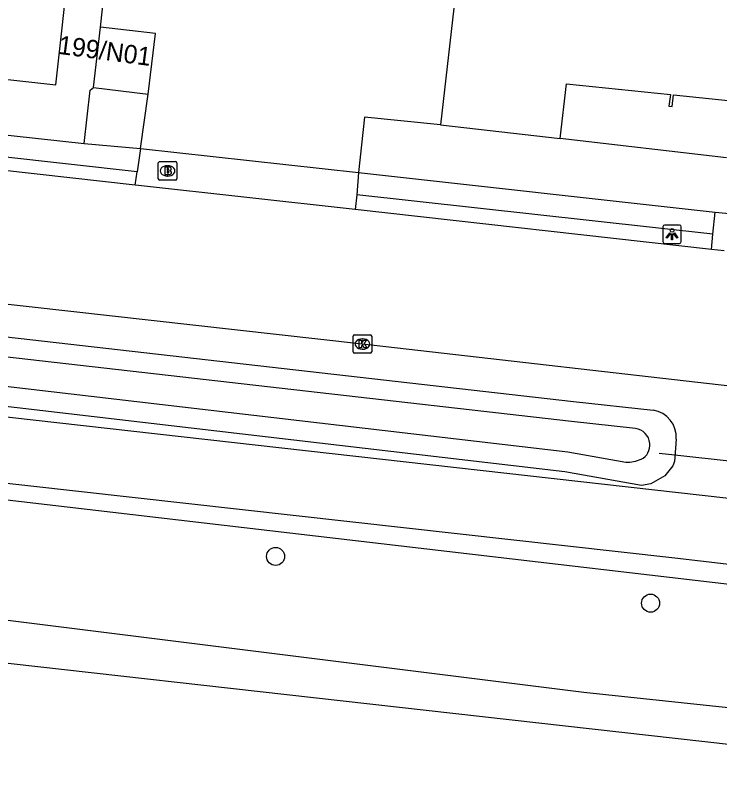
# Model space of a CAD drawing. Extents: x 161389 to 162585, y 388479 to 389761.
# Drawn here: x 162279.11 to 162317.29, y 388652.05 to 388693.41 of the extents above; entities that cross this region are included whole.
import ezdxf

# ---------------------------------------------------------------- set-up
doc = ezdxf.new("R2010")
doc.units = 0
for name, color, linetype in [('IMGEO_Berm_groen', 7, 'Continuous'), ('IMGEO_Boom', 7, 'Continuous'), ('IMGEO_Brandkraan', 7, 'Continuous'), ('IMGEO_Duiker', 7, 'Continuous'), ('IMGEO_Fietspad_gesloten', 7, 'Continuous'), ('IMGEO_Groenvoorziening', 7, 'Continuous'), ('IMGEO_Kolk', 7, 'Continuous'), ('IMGEO_Lichtpunt', 7, 'Continuous'), ('IMGEO_Pand', 7, 'Continuous'), ('IMGEO_Pand_nummerreeks', 7, 'Continuous'), ('IMGEO_Rijbaan_lokaal_gesloten', 7, 'Continuous'), ('IMGEO_Rijbaan_lokaal_open', 7, 'Continuous'), ('IMGEO_Voetpad_open', 7, 'Continuous'), ('IMGEO_Waterloop', 7, 'Continuous')]:
    doc.layers.add(name, color=color, linetype=linetype)

msp = doc.modelspace()

# ---------------------------------------------------------------- linework, layer by layer
at = {"layer": 'IMGEO_Berm_groen'}
for points in [[(162195.511, 388685.399), (162199.258, 388685.044), (162309.372, 388672.493), (162313.677, 388672.019)], [(162314.929, 388670.455), (162314.838, 388669.228), (162314.739, 388669.003), (162314.316, 388668.451), (162313.561, 388668.026), (162313.044, 388667.945), (162308.893, 388668.677), (162198.797, 388681.534), (162194.824, 388681.685), (162194.516, 388681.817), (162194.124, 388682.146), (162193.837, 388682.714), (162193.797, 388682.968), (162193.974, 388684.393)], [(162244.211, 388671.327), (162267.366, 388668.474), (162328.021, 388661.404)]]:
    msp.add_lwpolyline(points, dxfattribs=at)
msp.add_arc((162313.459, 388670.561), 1.474, 355.8563, 81.4991, dxfattribs=at)
at = {"layer": 'IMGEO_Boom'}
for centre in [(162293.214, 388664.093), (162313.541, 388661.562)]:
    msp.add_circle(centre, 0.489, dxfattribs=at)
at = {"layer": 'IMGEO_Brandkraan'}
for p, q in [((162286.934, 388685.481), (162287.786, 388685.481)), ((162286.859, 388684.555), (162286.859, 388685.407)), ((162287.347, 388685.261), (162287.372, 388685.261)), ((162287.86, 388685.407), (162287.86, 388684.555)), ((162287.37, 388684.701), (162287.345, 388684.701)), ((162287.786, 388684.481), (162286.934, 388684.481))]:
    msp.add_line(p, q, dxfattribs=at)
for points in [[(162286.934, 388685.481), (162287.786, 388685.481)], [(162286.859, 388684.555), (162286.859, 388685.407)], [(162287.207, 388685.181), (162287.207, 388684.781), (162287.42, 388684.781)], [(162287.438, 388685.181), (162287.207, 388685.181)], [(162287.386, 388685.1), (162287.332, 388685.1), (162287.332, 388685.024)], [(162287.86, 388685.407), (162287.86, 388684.555)], [(162287.332, 388685.024), (162287.385, 388685.024)], [(162287.394, 388684.948), (162287.332, 388684.948), (162287.332, 388684.867)], [(162287.332, 388684.867), (162287.394, 388684.867)], [(162287.786, 388684.481), (162286.934, 388684.481)]]:
    msp.add_lwpolyline(points, dxfattribs=at)
for centre, radius, start, end in [((162286.936, 388685.405), 0.0765, 91.552, 178.448), ((162286.936, 388685.405), 0.0765, 91.552, 178.448), ((162287.784, 388685.405), 0.0765, 1.552, 88.448), ((162287.784, 388685.405), 0.0765, 1.552, 88.448), ((162287.387, 388685.062), 0.0379, 267.8285, 90.9355), ((162287.442, 388685.036), 0.145, 59.4692, 91.5367), ((162287.467, 388685.083), 0.0922, 285.5137, 58.1501), ((162287.395, 388684.907), 0.0404, 269.8759, 90.5077), ((162287.426, 388685.032), 0.251, 268.6676, 293.5347), ((162287.472, 388684.891), 0.105, 301.3115, 78.989), ((162286.936, 388684.557), 0.0765, 181.552, 268.448), ((162286.936, 388684.557), 0.0765, 181.552, 268.448), ((162287.784, 388684.557), 0.0765, 271.552, 358.448), ((162287.784, 388684.557), 0.0765, 271.552, 358.448)]:
    msp.add_arc(centre, radius, start, end, dxfattribs=at)
for centre, major_axis, ratio, start_param, end_param in [((162287.346, 388684.981), (-0.387, 0.002), 0.722429, 4.712389, 7.853982), ((162287.371, 388684.981), (-0.39, 0.002), 0.717154, 1.570796, 4.712389)]:
    msp.add_ellipse(centre, major_axis=major_axis, ratio=ratio, start_param=start_param, end_param=end_param, dxfattribs=at)
at = {"layer": 'IMGEO_Duiker'}
msp.add_lwpolyline([(162351.516, 388665.549), (162350.544, 388665.656), (162342.711, 388666.516), (162342.022, 388666.592), (162328.189, 388668.111), (162327.769, 388668.157), (162314.864, 388669.574), (162314.015, 388669.667)], dxfattribs=at)
at = {"layer": 'IMGEO_Fietspad_gesloten'}
for points in [[(162190.209, 388681.612), (162327.081, 388666.21), (162327.212, 388666.322), (162327.332, 388666.446), (162327.44, 388666.58), (162327.536, 388666.723), (162327.619, 388666.874), (162327.689, 388667.031), (162327.743, 388667.195), (162327.783, 388667.362), (162327.808, 388667.533), (162327.818, 388667.705), (162327.812, 388667.877), (162327.791, 388668.048), (162327.769, 388668.157), (162327.723, 388668.324), (162327.662, 388668.485), (162327.587, 388668.641), (162327.498, 388668.789), (162327.396, 388668.929), (162327.347, 388668.988)], [(162328.163, 388662.672), (162327.44, 388662.75), (162327.383, 388662.532), (162314.863, 388664.007), (162212.05, 388675.493)]]:
    msp.add_lwpolyline(points, dxfattribs=at)
at = {"layer": 'IMGEO_Groenvoorziening'}
msp.add_lwpolyline([(162327.291, 388654.887), (162309.928, 388656.723), (162266.988, 388662.085), (162242.291, 388665.501), (162242.681, 388666.67)], dxfattribs=at)
at = {"layer": 'IMGEO_Kolk'}
for p, q in [((162297.424, 388675.175), (162297.424, 388676.027)), ((162297.499, 388676.101), (162298.351, 388676.101)), ((162298.425, 388676.027), (162298.425, 388675.175)), ((162297.912, 388675.881), (162297.937, 388675.881)), ((162297.935, 388675.321), (162297.91, 388675.321)), ((162298.351, 388675.101), (162297.499, 388675.101))]:
    msp.add_line(p, q, dxfattribs=at)
for points in [[(162297.424, 388675.175), (162297.424, 388676.027)], [(162297.499, 388676.101), (162298.351, 388676.101)], [(162298.425, 388676.027), (162298.425, 388675.175)], [(162297.745, 388675.801), (162297.868, 388675.801), (162297.868, 388675.65), (162297.998, 388675.801), (162298.162, 388675.801), (162298.016, 388675.65), (162298.169, 388675.401), (162298.017, 388675.401), (162297.932, 388675.565), (162297.868, 388675.498), (162297.868, 388675.401), (162297.745, 388675.401), (162297.745, 388675.801)], [(162298.351, 388675.101), (162297.499, 388675.101)]]:
    msp.add_lwpolyline(points, dxfattribs=at)
for centre, start, end in [((162297.501, 388676.025), 91.552, 178.448), ((162297.501, 388676.025), 91.552, 178.448), ((162298.349, 388676.025), 1.552, 88.448), ((162298.349, 388676.025), 1.552, 88.448), ((162297.501, 388675.177), 181.552, 268.448), ((162297.501, 388675.177), 181.552, 268.448), ((162298.349, 388675.177), 271.552, 358.448), ((162298.349, 388675.177), 271.552, 358.448)]:
    msp.add_arc(centre, 0.0765, start, end, dxfattribs=at)
for centre, major_axis, ratio, start_param, end_param in [((162297.911, 388675.601), (-0.387, 0.002), 0.722429, 4.712389, 7.853982), ((162297.936, 388675.601), (-0.39, 0.002), 0.717154, 1.570796, 4.712389)]:
    msp.add_ellipse(centre, major_axis=major_axis, ratio=ratio, start_param=start_param, end_param=end_param, dxfattribs=at)
at = {"layer": 'IMGEO_Lichtpunt'}
for p, q in [((162314.205, 388681.953), (162314.205, 388681.146)), ((162314.205, 388681.953), (162314.205, 388681.146)), ((162315.107, 388682.048), (162314.299, 388682.048)), ((162315.107, 388682.048), (162314.299, 388682.048)), ((162315.201, 388681.146), (162315.201, 388681.953)), ((162315.201, 388681.146), (162315.201, 388681.953)), ((162314.299, 388681.052), (162315.107, 388681.052)), ((162314.299, 388681.052), (162315.107, 388681.052))]:
    msp.add_line(p, q, dxfattribs=at)
for points in [[(162314.579, 388681.617), (162314.618, 388681.589), (162314.43, 388681.327), (162314.392, 388681.354), (162314.579, 388681.617)], [(162314.681, 388681.569), (162314.728, 388681.569), (162314.728, 388681.247), (162314.681, 388681.247), (162314.681, 388681.569)], [(162314.791, 388681.589), (162314.829, 388681.616), (162315.016, 388681.354), (162314.977, 388681.326), (162314.791, 388681.589)]]:
    msp.add_lwpolyline(points, dxfattribs=at)
msp.add_circle((162314.704, 388681.751), 0.0994, dxfattribs=at)
for centre, start, end in [((162314.299, 388681.953), 90, 180), ((162314.299, 388681.953), 90, 180), ((162315.107, 388681.953), 0, 90), ((162315.107, 388681.953), 0, 90), ((162314.299, 388681.146), 180, 270), ((162314.299, 388681.146), 180, 270), ((162315.107, 388681.146), 270, 0), ((162315.107, 388681.146), 270, 360)]:
    msp.add_arc(centre, 0.0946, start, end, dxfattribs=at)
at = {"layer": 'IMGEO_Pand'}
for points in [[(162266.146, 388697.835), (162265.455, 388691.401), (162281.314, 388689.643), (162282.073, 388696.501), (162284.111, 388696.275)], [(162297.05, 388695.111), (162302.955, 388694.443), (162302.151, 388687.471)], [(162283.34, 388689.498), (162283.731, 388692.772)], [(162286.316, 388689.142), (162286.707, 388692.416), (162283.731, 388692.772)], [(162308.649, 388686.731), (162308.988, 388689.701), (162314.627, 388689.125), (162314.534, 388688.49), (162314.719, 388688.469), (162314.789, 388689.095), (162320.535, 388688.495), (162320.465, 388687.859), (162320.653, 388687.85), (162320.683, 388688.479), (162325.071, 388688.022)], [(162283.34, 388689.498), (162286.316, 388689.142)], [(162302.151, 388687.471), (162308.649, 388686.731)], [(162323.903, 388652.051), (162324.031, 388653.194), (162250.099, 388661.511), (162249.582, 388661.569), (162249.555, 388661.32)]]:
    msp.add_lwpolyline(points, dxfattribs=at)
at = {"layer": 'IMGEO_Rijbaan_lokaal_gesloten'}
for points in [[(162190.731, 388687.591), (162191.691, 388687.487), (162192.948, 388687.248), (162200.409, 388686.41), (162212.852, 388685.186), (162234.573, 388682.697), (162256.569, 388680.26), (162277.429, 388677.907), (162297.925, 388675.602), (162319.739, 388673.126), (162319.871, 388673.113), (162320.835, 388672.971)], [(162285.607, 388684.214), (162265.796, 388686.429)], [(162297.525, 388682.881), (162285.793, 388684.193), (162285.607, 388684.214)], [(162316.844, 388680.72), (162297.525, 388682.881)], [(162317.536, 388680.643), (162316.844, 388680.72)]]:
    msp.add_lwpolyline(points, dxfattribs=at)
at = {"layer": 'IMGEO_Rijbaan_lokaal_open'}
for points in [[(162283.731, 388692.772), (162284.111, 388696.275)], [(162285.892, 388686.196), (162286.316, 388689.142)], [(162302.151, 388687.471), (162298.032, 388687.897), (162297.703, 388684.885)], [(162285.892, 388686.196), (162297.703, 388684.885)]]:
    msp.add_lwpolyline(points, dxfattribs=at)
at = {"layer": 'IMGEO_Voetpad_open'}
for points in [[(162282.834, 388686.471), (162283.168, 388689.347), (162283.34, 388689.498)], [(162265.999, 388688.392), (162267.535, 388688.159), (162271.112, 388687.748), (162282.834, 388686.471)], [(162285.711, 388684.934), (162270.971, 388686.569), (162265.86, 388687.132)], [(162317.656, 388685.68), (162308.649, 388686.731)], [(162282.834, 388686.471), (162285.892, 388686.196)], [(162285.892, 388686.196), (162285.711, 388684.934)], [(162317.042, 388682.74), (162318.194, 388682.629), (162319.35, 388682.621), (162320.503, 388682.717), (162321.643, 388682.915), (162322.761, 388683.214), (162323.847, 388683.612), (162324.894, 388684.105), (162325.892, 388684.69), (162326.834, 388685.362), (162327.076, 388685.556)], [(162285.607, 388684.214), (162285.711, 388684.934)], [(162297.703, 388684.885), (162297.614, 388683.685)], [(162297.703, 388684.885), (162317.042, 388682.74)], [(162297.614, 388683.685), (162297.525, 388682.881)], [(162316.918, 388681.559), (162297.614, 388683.685)], [(162316.918, 388681.559), (162317.042, 388682.74)], [(162316.844, 388680.72), (162316.918, 388681.559)]]:
    msp.add_lwpolyline(points, dxfattribs=at)
at = {"layer": 'IMGEO_Waterloop'}
for points in [[(162312.727, 388671.029), (162309.251, 388671.412), (162199.145, 388683.962), (162195.97, 388684.262)], [(162195.347, 388683.225), (162195.481, 388683.01), (162195.633, 388682.868), (162195.82, 388682.736), (162198.881, 388682.62), (162309.051, 388669.754), (162312.207, 388669.198)]]:
    msp.add_lwpolyline(points, dxfattribs=at)
for centre, radius, start, end in [((162312.582, 388670.116), 0.925, 6.2881, 80.9669), ((162312.664, 388670.121), 0.843, 295.2384, 6.5731), ((162312.244, 388671.169), 1.971, 268.917, 293.2704)]:
    msp.add_arc(centre, radius, start, end, dxfattribs=at)

# ---------------------------------------------------------------- texts
at = {"layer": 'IMGEO_Pand_nummerreeks'}
msp.add_text('199/N01', height=1, rotation=352.4468, dxfattribs=at).set_placement((162281.391, 388691.326))

doc.saveas('drawing.dxf')
